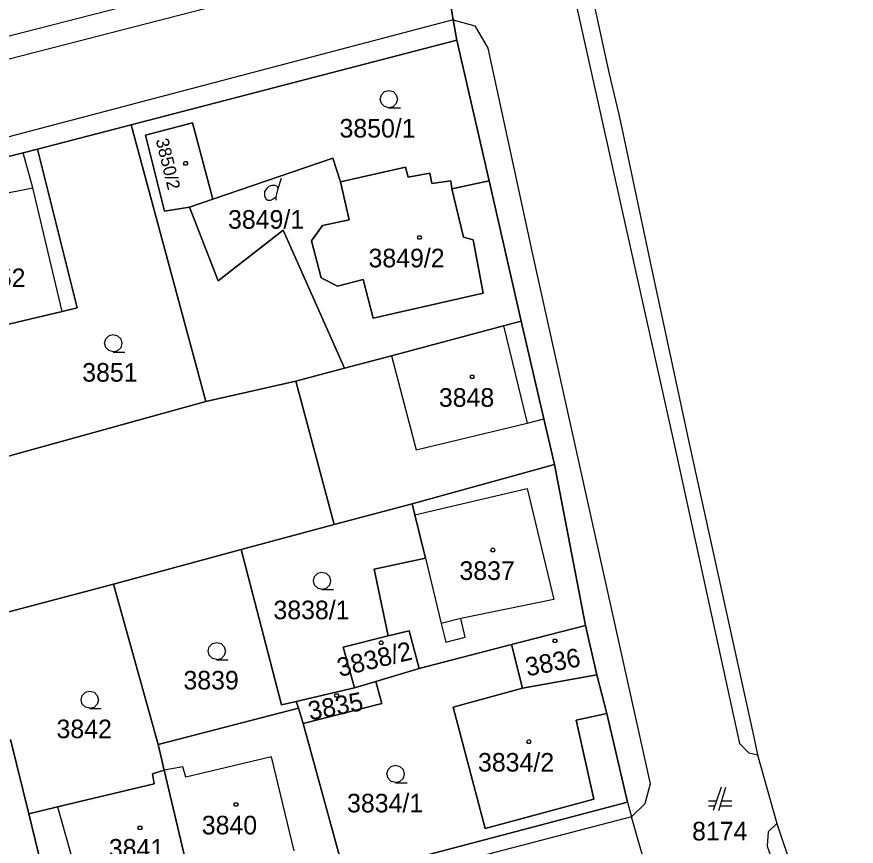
# Model space of a CAD drawing. Extents: x -263587 to -261993, y -1238795 to -1236748.
# Drawn here: x -262692.3 to -262620.1, y -1238113.2 to -1238041.9 of the extents above; entities that cross this region are included whole.
import ezdxf

# ---------------------------------------------------------------- set-up
doc = ezdxf.new("R2010")
doc.units = 0
doc.layers.add('Vrstva 1', color=7, linetype='Continuous')

msp = doc.modelspace()

# ---------------------------------------------------------------- linework, layer by layer
at = {"layer": 'Vrstva 1'}
for p, q in [((-262650.42, -1238012.79), (-262643.91, -1238042.02)), ((-262656.29, -1238034.17), (-262695.7, -1238044.27)), ((-262655.81, -1238035.98), (-262720.41, -1238052.64)), ((-262655.81, -1238035.98), (-262654.73, -1238042.16)), ((-262654.73, -1238042.16), (-262655.81, -1238035.98)), ((-262643.22, -1238038.15), (-262641.34, -1238046.7)), ((-262643.91, -1238042.02), (-262635.68, -1238078.9)), ((-262654.73, -1238042.16), (-262723.17, -1238060.18)), ((-262654.73, -1238042.16), (-262654.42, -1238043.91)), ((-262654.42, -1238043.91), (-262654.73, -1238042.16)), ((-262654.73, -1238042.16), (-262652.87, -1238042.67)), ((-262652.87, -1238042.67), (-262651.75, -1238044.61)), ((-262682.42, -1238051.19), (-262654.42, -1238043.91)), ((-262654.42, -1238043.91), (-262682.42, -1238051.19)), ((-262654.42, -1238043.91), (-262651.63, -1238056.02)), ((-262651.63, -1238056.02), (-262654.42, -1238043.91)), ((-262651.75, -1238044.61), (-262647.84, -1238062.72)), ((-262641.34, -1238046.7), (-262640.49, -1238050.31)), ((-262640.49, -1238050.31), (-262640.24, -1238051.48)), ((-262690.47, -1238053.29), (-262682.42, -1238051.19)), ((-262682.42, -1238051.19), (-262690.47, -1238053.29)), ((-262682.42, -1238051.19), (-262676.02, -1238074.99)), ((-262676.02, -1238074.99), (-262682.42, -1238051.19)), ((-262677.15, -1238051.03), (-262681.19, -1238052.09)), ((-262681.19, -1238052.09), (-262677.15, -1238051.03)), ((-262675.41, -1238057.58), (-262677.15, -1238051.03)), ((-262677.15, -1238051.03), (-262675.41, -1238057.58)), ((-262681.19, -1238052.09), (-262679.55, -1238058.62)), ((-262679.55, -1238058.62), (-262681.19, -1238052.09)), ((-262640.24, -1238051.48), (-262637.7, -1238063.41)), ((-262701.92, -1238056.1), (-262691.71, -1238053.59)), ((-262691.71, -1238053.59), (-262701.92, -1238056.1)), ((-262691.71, -1238053.59), (-262690.47, -1238053.29)), ((-262690.47, -1238053.29), (-262691.71, -1238053.59)), ((-262690.89, -1238056.62), (-262691.71, -1238053.59)), ((-262690.47, -1238053.29), (-262687.06, -1238066.94)), ((-262687.06, -1238066.94), (-262690.47, -1238053.29)), ((-262665.1, -1238054.05), (-262675.41, -1238057.58)), ((-262675.41, -1238057.58), (-262665.1, -1238054.05)), ((-262664.44, -1238056.1), (-262665.1, -1238054.05)), ((-262665.1, -1238054.05), (-262664.44, -1238056.1)), ((-262658.84, -1238054.83), (-262664.44, -1238056.1)), ((-262664.44, -1238056.1), (-262658.84, -1238054.83)), ((-262658.6, -1238055.7), (-262658.84, -1238054.83)), ((-262658.84, -1238054.83), (-262658.6, -1238055.7)), ((-262656.76, -1238055.35), (-262658.6, -1238055.7)), ((-262658.6, -1238055.7), (-262656.76, -1238055.35)), ((-262656.57, -1238056.25), (-262656.76, -1238055.35)), ((-262656.76, -1238055.35), (-262656.57, -1238056.25)), ((-262669.78, -1238056.67), (-262669.51, -1238055.77)), ((-262663.67, -1238059.36), (-262664.44, -1238056.1)), ((-262664.44, -1238056.1), (-262663.67, -1238059.36)), ((-262654.94, -1238056), (-262656.57, -1238056.25)), ((-262656.57, -1238056.25), (-262654.94, -1238056)), ((-262654.84, -1238056.7), (-262654.94, -1238056)), ((-262654.94, -1238056), (-262654.84, -1238056.7)), ((-262651.63, -1238056.02), (-262654.84, -1238056.7)), ((-262654.84, -1238056.7), (-262651.63, -1238056.02)), ((-262648.88, -1238068.08), (-262651.63, -1238056.02)), ((-262651.63, -1238056.02), (-262648.88, -1238068.08)), ((-262701.26, -1238058.68), (-262690.89, -1238056.62)), ((-262688.37, -1238067.25), (-262690.89, -1238056.62)), ((-262654.84, -1238056.7), (-262653.86, -1238060.85)), ((-262653.86, -1238060.85), (-262654.84, -1238056.7)), ((-262675.41, -1238057.58), (-262677.42, -1238058.28)), ((-262677.42, -1238058.28), (-262675.41, -1238057.58)), ((-262679.55, -1238058.62), (-262677.42, -1238058.28)), ((-262677.42, -1238058.28), (-262679.55, -1238058.62)), ((-262677.42, -1238058.28), (-262674.95, -1238064.6)), ((-262674.95, -1238064.6), (-262677.42, -1238058.28)), ((-262665.97, -1238059.86), (-262663.67, -1238059.36)), ((-262663.67, -1238059.36), (-262665.97, -1238059.86)), ((-262666.92, -1238061.17), (-262665.97, -1238059.86)), ((-262665.97, -1238059.86), (-262666.92, -1238061.17)), ((-262674.95, -1238064.6), (-262669.35, -1238060.26)), ((-262669.35, -1238060.26), (-262674.95, -1238064.6)), ((-262669.35, -1238060.26), (-262664.09, -1238072.13)), ((-262664.09, -1238072.13), (-262669.35, -1238060.26)), ((-262666.08, -1238064.34), (-262666.92, -1238061.17)), ((-262666.92, -1238061.17), (-262666.08, -1238064.34)), ((-262653.86, -1238060.85), (-262653.03, -1238061.08)), ((-262653.03, -1238061.08), (-262653.86, -1238060.85)), ((-262653.03, -1238061.08), (-262652.17, -1238065.68)), ((-262652.17, -1238065.68), (-262653.03, -1238061.08)), ((-262647.84, -1238062.72), (-262637.8, -1238107.86)), ((-262637.7, -1238063.41), (-262634.44, -1238078.59)), ((-262664.69, -1238065.06), (-262666.08, -1238064.34)), ((-262666.08, -1238064.34), (-262664.69, -1238065.06)), ((-262662.47, -1238064.5), (-262664.69, -1238065.06)), ((-262664.69, -1238065.06), (-262662.47, -1238064.5)), ((-262661.61, -1238067.82), (-262662.47, -1238064.5)), ((-262662.47, -1238064.5), (-262661.61, -1238067.82)), ((-262652.17, -1238065.68), (-262661.61, -1238067.82)), ((-262661.61, -1238067.82), (-262652.17, -1238065.68)), ((-262688.37, -1238067.25), (-262698.3, -1238069.61)), ((-262698.3, -1238069.61), (-262688.37, -1238067.25)), ((-262687.06, -1238066.94), (-262688.37, -1238067.25)), ((-262688.37, -1238067.25), (-262687.06, -1238066.94)), ((-262660.04, -1238071.05), (-262650.41, -1238068.49)), ((-262650.41, -1238068.49), (-262660.04, -1238071.05)), ((-262650.41, -1238068.49), (-262648.88, -1238068.08)), ((-262648.88, -1238068.08), (-262650.41, -1238068.49)), ((-262650.41, -1238068.49), (-262648.39, -1238076.84)), ((-262648.88, -1238068.08), (-262646.93, -1238076.49)), ((-262646.93, -1238076.49), (-262648.88, -1238068.08)), ((-262664.09, -1238072.13), (-262660.04, -1238071.05)), ((-262660.04, -1238071.05), (-262664.09, -1238072.13)), ((-262660.04, -1238071.05), (-262657.93, -1238079.14)), ((-262664.09, -1238072.13), (-262668.28, -1238073.25)), ((-262668.28, -1238073.25), (-262664.09, -1238072.13)), ((-262668.28, -1238073.25), (-262676.02, -1238074.99)), ((-262676.02, -1238074.99), (-262668.28, -1238073.25)), ((-262664.96, -1238085.55), (-262668.28, -1238073.25)), ((-262668.28, -1238073.25), (-262664.96, -1238085.55)), ((-262676.02, -1238074.99), (-262694.98, -1238080.24)), ((-262694.98, -1238080.24), (-262676.02, -1238074.99)), ((-262648.39, -1238076.84), (-262646.93, -1238076.49)), ((-262646.93, -1238076.49), (-262646.02, -1238080.41)), ((-262646.02, -1238080.41), (-262646.93, -1238076.49)), ((-262657.93, -1238079.14), (-262648.39, -1238076.84)), ((-262634.44, -1238078.59), (-262628.89, -1238103.84)), ((-262635.68, -1238078.9), (-262630.12, -1238104.4)), ((-262646.02, -1238080.41), (-262658.27, -1238083.78)), ((-262658.27, -1238083.78), (-262646.02, -1238080.41)), ((-262646.02, -1238080.41), (-262643.35, -1238094.24)), ((-262643.35, -1238094.24), (-262646.02, -1238080.41)), ((-262658.04, -1238084.73), (-262648.39, -1238082.46)), ((-262648.39, -1238082.46), (-262646.09, -1238092.02)), ((-262658.27, -1238083.78), (-262664.96, -1238085.55)), ((-262664.96, -1238085.55), (-262658.27, -1238083.78)), ((-262658.04, -1238084.73), (-262658.27, -1238083.78)), ((-262658.27, -1238083.78), (-262658.04, -1238084.73)), ((-262657.13, -1238088.47), (-262658.04, -1238084.73)), ((-262658.04, -1238084.73), (-262657.13, -1238088.47)), ((-262672.97, -1238087.7), (-262664.96, -1238085.55)), ((-262664.96, -1238085.55), (-262672.97, -1238087.7)), ((-262672.97, -1238087.7), (-262683.95, -1238090.7)), ((-262683.95, -1238090.7), (-262672.97, -1238087.7)), ((-262669.5, -1238101.07), (-262672.97, -1238087.7)), ((-262672.97, -1238087.7), (-262669.5, -1238101.07)), ((-262661.53, -1238089.41), (-262657.13, -1238088.47)), ((-262657.13, -1238088.47), (-262661.53, -1238089.41)), ((-262657.13, -1238088.47), (-262655.77, -1238094.07)), ((-262660.33, -1238095.13), (-262661.53, -1238089.41)), ((-262661.53, -1238089.41), (-262660.33, -1238095.13)), ((-262683.95, -1238090.7), (-262695.35, -1238093.71)), ((-262695.35, -1238093.71), (-262683.95, -1238090.7)), ((-262683.95, -1238090.7), (-262680.11, -1238104.49)), ((-262680.11, -1238104.49), (-262683.95, -1238090.7)), ((-262646.09, -1238092.02), (-262654.09, -1238093.66)), ((-262654.09, -1238093.66), (-262655.77, -1238094.07)), ((-262653.7, -1238095.26), (-262654.09, -1238093.66)), ((-262658.52, -1238094.71), (-262660.33, -1238095.13)), ((-262660.33, -1238095.13), (-262658.52, -1238094.71)), ((-262657.67, -1238097.95), (-262658.52, -1238094.71)), ((-262658.52, -1238094.71), (-262657.67, -1238097.95)), ((-262655.77, -1238094.07), (-262655.38, -1238095.67)), ((-262643.35, -1238094.24), (-262649.71, -1238095.88)), ((-262649.71, -1238095.88), (-262643.35, -1238094.24)), ((-262643.35, -1238094.24), (-262642.39, -1238098.48)), ((-262642.39, -1238098.48), (-262643.35, -1238094.24)), ((-262660.33, -1238095.13), (-262664.21, -1238096.11)), ((-262664.21, -1238096.11), (-262660.33, -1238095.13)), ((-262655.38, -1238095.67), (-262653.7, -1238095.26)), ((-262664.21, -1238096.11), (-262663.23, -1238099.61)), ((-262663.23, -1238099.61), (-262664.21, -1238096.11)), ((-262649.71, -1238095.88), (-262657.67, -1238097.95)), ((-262657.67, -1238097.95), (-262649.71, -1238095.88)), ((-262649.71, -1238095.88), (-262648.79, -1238099.64)), ((-262648.79, -1238099.64), (-262649.71, -1238095.88)), ((-262657.67, -1238097.95), (-262661.38, -1238099.06)), ((-262661.38, -1238099.06), (-262657.67, -1238097.95)), ((-262661.38, -1238099.06), (-262663.23, -1238099.61)), ((-262663.23, -1238099.61), (-262661.38, -1238099.06)), ((-262661.38, -1238099.06), (-262660.87, -1238100.95)), ((-262660.87, -1238100.95), (-262661.38, -1238099.06)), ((-262648.79, -1238099.64), (-262642.39, -1238098.48)), ((-262642.39, -1238098.48), (-262648.79, -1238099.64)), ((-262642.39, -1238098.48), (-262641.52, -1238101.82)), ((-262641.52, -1238101.82), (-262642.39, -1238098.48)), ((-262663.23, -1238099.61), (-262668.23, -1238100.77)), ((-262668.23, -1238100.77), (-262663.23, -1238099.61)), ((-262648.79, -1238099.64), (-262654.73, -1238101.27)), ((-262654.73, -1238101.27), (-262648.79, -1238099.64)), ((-262668.23, -1238100.77), (-262669.5, -1238101.07)), ((-262669.5, -1238101.07), (-262668.23, -1238100.77)), ((-262668.23, -1238100.77), (-262668.05, -1238101.36)), ((-262668.05, -1238101.36), (-262668.23, -1238100.77)), ((-262660.87, -1238100.95), (-262667.65, -1238102.68)), ((-262667.65, -1238102.68), (-262660.87, -1238100.95)), ((-262668.05, -1238101.36), (-262680.11, -1238104.49)), ((-262680.11, -1238104.49), (-262668.05, -1238101.36)), ((-262667.65, -1238102.68), (-262668.05, -1238101.36)), ((-262668.05, -1238101.36), (-262667.65, -1238102.68)), ((-262654.73, -1238101.27), (-262651.99, -1238111.7)), ((-262651.99, -1238111.7), (-262654.73, -1238101.27)), ((-262644.17, -1238102.4), (-262641.52, -1238101.82)), ((-262641.52, -1238101.82), (-262644.17, -1238102.4)), ((-262641.52, -1238101.82), (-262639.75, -1238109.44)), ((-262639.75, -1238109.44), (-262641.52, -1238101.82)), ((-262667.65, -1238102.68), (-262664.03, -1238115.82)), ((-262664.03, -1238115.82), (-262667.65, -1238102.68)), ((-262642.63, -1238109.19), (-262644.17, -1238102.4)), ((-262644.17, -1238102.4), (-262642.63, -1238109.19)), ((-262692.82, -1238104.05), (-262691.22, -1238110.44)), ((-262691.22, -1238110.44), (-262692.82, -1238104.05)), ((-262628.89, -1238103.84), (-262628.57, -1238105.36)), ((-262680.11, -1238104.49), (-262679.59, -1238106.68)), ((-262679.59, -1238106.68), (-262680.11, -1238104.49)), ((-262630.12, -1238104.4), (-262629.3, -1238105.2)), ((-262670.37, -1238105.54), (-262677.74, -1238107.28)), ((-262668.4, -1238113.62), (-262670.37, -1238105.54)), ((-262629.3, -1238105.2), (-262628.57, -1238105.36)), ((-262628.57, -1238105.36), (-262626.92, -1238111.26)), ((-262680.59, -1238107.01), (-262679.59, -1238106.68)), ((-262679.59, -1238106.68), (-262680.59, -1238107.01)), ((-262680.44, -1238107.87), (-262680.59, -1238107.01)), ((-262680.59, -1238107.01), (-262680.44, -1238107.87)), ((-262677.98, -1238106.4), (-262679.59, -1238106.68)), ((-262679.59, -1238106.68), (-262677.47, -1238115.57)), ((-262677.47, -1238115.57), (-262679.59, -1238106.68)), ((-262677.74, -1238107.28), (-262677.98, -1238106.4)), ((-262688.75, -1238109.85), (-262680.44, -1238107.87)), ((-262680.44, -1238107.87), (-262688.75, -1238109.85)), ((-262637.8, -1238107.86), (-262638.25, -1238109.59)), ((-262631.68, -1238108.16), (-262632.38, -1238110.16)), ((-262631.88, -1238110.16), (-262631.28, -1238108.16)), ((-262691.22, -1238110.44), (-262688.75, -1238109.85)), ((-262688.75, -1238109.85), (-262691.22, -1238110.44)), ((-262688.75, -1238109.85), (-262686.39, -1238118.33)), ((-262639.75, -1238109.44), (-262664.03, -1238115.82)), ((-262664.03, -1238115.82), (-262639.75, -1238109.44)), ((-262651.99, -1238111.7), (-262642.63, -1238109.19)), ((-262642.63, -1238109.19), (-262651.99, -1238111.7)), ((-262639.75, -1238109.44), (-262639.39, -1238110.71)), ((-262638.25, -1238109.59), (-262639.39, -1238110.71)), ((-262632.1, -1238109.36), (-262632.78, -1238109.36)), ((-262632.78, -1238109.76), (-262632.24, -1238109.76)), ((-262631.76, -1238109.76), (-262630.78, -1238109.76)), ((-262630.78, -1238109.36), (-262631.64, -1238109.36)), ((-262691.22, -1238110.44), (-262688.49, -1238121.81)), ((-262688.49, -1238121.81), (-262691.22, -1238110.44)), ((-262639.39, -1238110.71), (-262684.26, -1238122.35)), ((-262637.94, -1238115.76), (-262639.39, -1238110.71)), ((-262626.92, -1238111.26), (-262627.64, -1238111.98)), ((-262626.92, -1238111.26), (-262626.4, -1238112.83)), ((-262627.64, -1238111.98), (-262627.75, -1238113.21)), ((-262627.75, -1238113.21), (-262620.08, -1238134.19)), ((-262626.4, -1238112.83), (-262623.18, -1238121.91))]:
    msp.add_line(p, q, dxfattribs=at)
for points in [[(-262660.26, -1238049.72), (-262660.64, -1238049.62), (-262660.91, -1238049.35), (-262661.01, -1238048.98), (-262660.91, -1238048.61), (-262660.64, -1238048.34), (-262660.27, -1238048.24), (-262659.9, -1238048.34), (-262659.63, -1238048.61), (-262659.53, -1238048.99), (-262659.63, -1238049.37), (-262659.9, -1238049.64), (-262660.28, -1238049.74), (-262659.28, -1238049.74)], [(-262669.96, -1238057.66), (-262669.96, -1238057.39), (-262669.78, -1238056.67), (-262669.87, -1238056.49), (-262670.05, -1238056.4), (-262670.32, -1238056.4), (-262670.59, -1238056.49), (-262670.77, -1238056.67), (-262670.95, -1238056.94), (-262670.95, -1238057.3), (-262670.86, -1238057.57), (-262670.68, -1238057.66), (-262670.41, -1238057.66), (-262670.23, -1238057.57), (-262669.96, -1238057.39)], [(-262683.96, -1238070.71), (-262684.34, -1238070.61), (-262684.61, -1238070.34), (-262684.71, -1238069.97), (-262684.61, -1238069.6), (-262684.34, -1238069.33), (-262683.97, -1238069.23), (-262683.6, -1238069.33), (-262683.33, -1238069.6), (-262683.23, -1238069.98), (-262683.33, -1238070.36), (-262683.6, -1238070.63), (-262683.98, -1238070.73), (-262682.98, -1238070.73)], [(-262666.01, -1238091.14), (-262666.39, -1238091.04), (-262666.66, -1238090.77), (-262666.76, -1238090.4), (-262666.66, -1238090.03), (-262666.39, -1238089.76), (-262666.02, -1238089.66), (-262665.65, -1238089.76), (-262665.38, -1238090.03), (-262665.28, -1238090.41), (-262665.38, -1238090.79), (-262665.65, -1238091.06), (-262666.03, -1238091.16), (-262665.03, -1238091.16)], [(-262675.06, -1238097.18), (-262675.44, -1238097.08), (-262675.71, -1238096.81), (-262675.81, -1238096.44), (-262675.71, -1238096.07), (-262675.44, -1238095.8), (-262675.07, -1238095.7), (-262674.7, -1238095.8), (-262674.43, -1238096.07), (-262674.33, -1238096.45), (-262674.43, -1238096.83), (-262674.7, -1238097.1), (-262675.08, -1238097.2), (-262674.08, -1238097.2)], [(-262685.98, -1238101.37), (-262686.36, -1238101.27), (-262686.63, -1238101), (-262686.73, -1238100.63), (-262686.63, -1238100.26), (-262686.36, -1238099.99), (-262685.99, -1238099.89), (-262685.62, -1238099.99), (-262685.35, -1238100.26), (-262685.25, -1238100.64), (-262685.35, -1238101.02), (-262685.62, -1238101.29), (-262686, -1238101.39), (-262685, -1238101.39)], [(-262659.68, -1238107.75), (-262660.06, -1238107.65), (-262660.33, -1238107.38), (-262660.43, -1238107.01), (-262660.33, -1238106.64), (-262660.06, -1238106.37), (-262659.69, -1238106.27), (-262659.32, -1238106.37), (-262659.05, -1238106.64), (-262658.95, -1238107.02), (-262659.05, -1238107.4), (-262659.32, -1238107.67), (-262659.7, -1238107.77), (-262658.7, -1238107.77)]]:
    msp.add_lwpolyline(points, dxfattribs=at)
for points in [[(-262677.66, -1238054.36), (-262677.57, -1238054.51), (-262677.66, -1238054.66), (-262677.84, -1238054.66), (-262677.93, -1238054.51), (-262677.84, -1238054.36)], [(-262657.55, -1238060.73), (-262657.46, -1238060.88), (-262657.55, -1238061.03), (-262657.73, -1238061.03), (-262657.82, -1238060.88), (-262657.73, -1238060.73)], [(-262653.01, -1238072.72), (-262652.92, -1238072.87), (-262653.01, -1238073.02), (-262653.19, -1238073.02), (-262653.28, -1238072.87), (-262653.19, -1238072.72)], [(-262651.24, -1238087.61), (-262651.15, -1238087.76), (-262651.24, -1238087.91), (-262651.42, -1238087.91), (-262651.51, -1238087.76), (-262651.42, -1238087.61)], [(-262645.9, -1238095.41), (-262645.81, -1238095.56), (-262645.9, -1238095.71), (-262646.08, -1238095.71), (-262646.17, -1238095.56), (-262646.08, -1238095.41)], [(-262660.84, -1238095.58), (-262660.75, -1238095.73), (-262660.84, -1238095.88), (-262661.02, -1238095.88), (-262661.11, -1238095.73), (-262661.02, -1238095.58)], [(-262664.67, -1238100.12), (-262664.58, -1238100.27), (-262664.67, -1238100.42), (-262664.85, -1238100.42), (-262664.94, -1238100.27), (-262664.85, -1238100.12)], [(-262648.14, -1238104.09), (-262648.05, -1238104.24), (-262648.14, -1238104.39), (-262648.32, -1238104.39), (-262648.41, -1238104.24), (-262648.32, -1238104.09)], [(-262673.33, -1238109.49), (-262673.24, -1238109.64), (-262673.33, -1238109.79), (-262673.51, -1238109.79), (-262673.6, -1238109.64), (-262673.51, -1238109.49)], [(-262681.58, -1238111.49), (-262681.49, -1238111.64), (-262681.58, -1238111.79), (-262681.76, -1238111.79), (-262681.85, -1238111.64), (-262681.76, -1238111.49)]]:
    msp.add_lwpolyline(points, close=True, dxfattribs=at)

# ---------------------------------------------------------------- texts
for s, p in [('3850/1', (-262664.513, -1238052.29)), ('3849/1', (-262674.1, -1238060.13)), ('3849/2', (-262662.019, -1238063.45)), ('3852', (-262696.278, -1238065.15)), ('3851', (-262686.639, -1238073.28)), ('3848', (-262655.968, -1238075.44)), ('3837', (-262654.198, -1238090.33)), ('3838/1', (-262670.194, -1238093.71)), ('3839', (-262677.934, -1238099.75)), ('3842', (-262688.848, -1238103.94)), ('3834/2', (-262652.603, -1238106.81)), ('3834/1', (-262663.864, -1238110.32)), ('3840', (-262676.357, -1238112.21)), ('8174', (-262634.194, -1238112.73)), ('3841', (-262684.349, -1238114.21))]:
    msp.add_text(s, height=1.6, dxfattribs=at).set_placement(p)
for s, height, rotation, p in [('3850/2', 1.1, 283.786, (-262680.323, -1238052.5)), ('3838/2', 1.6, 13.5218, (-262664.505, -1238098.677)), ('3836', 1.6, 10.8289, (-262648.364, -1238098.63)), ('3835', 1.6, 10.8289, (-262667.051, -1238102.411))]:
    msp.add_text(s, height=height, rotation=rotation, dxfattribs=at).set_placement(p)

doc.saveas('drawing.dxf')
